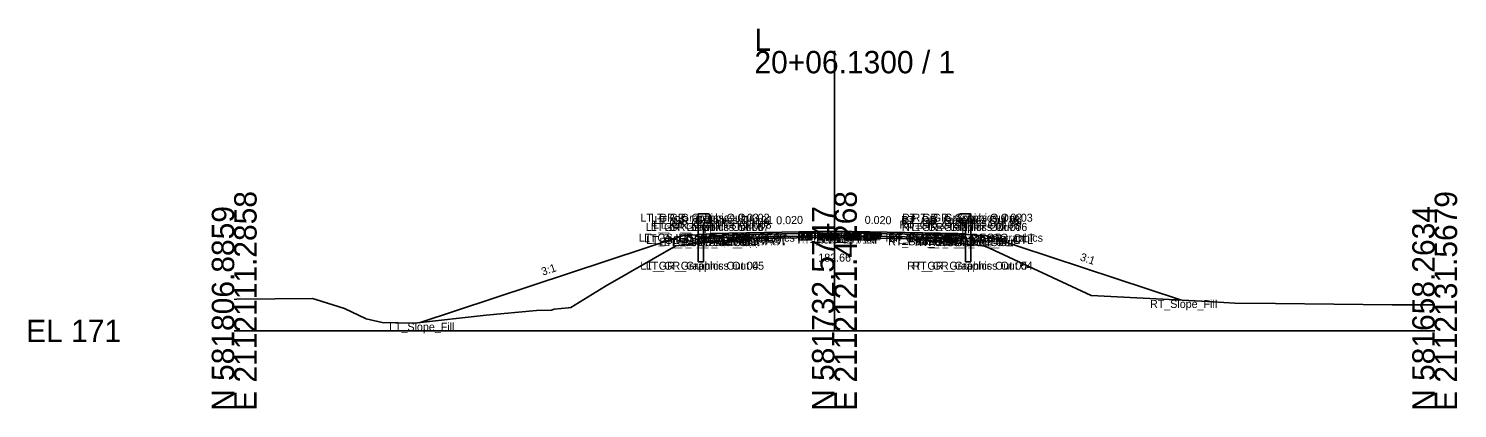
# Model space of a CAD drawing. Extents: x -26 to 3453, y -333 to 9539.
# Drawn here: x 3274.3 to 3452.8, y 1490.3 to 1537.8 of the extents above; entities that cross this region are included whole.
import ezdxf

# ---------------------------------------------------------------- set-up
doc = ezdxf.new("R2010")
doc.units = 0
for name, color, linetype in [('Default', 7, 'Continuous'), ('Exist Cross Section Cell', 7, 'Continuous'), ('Exist XS Ground Line', 7, 'Continuous'), ('Prop CMT Guardrail Graphics', 7, 'Continuous'), ('Prop CMT Pvmt Course 1', 7, 'Continuous'), ('Prop CMT Pvmt Course 2', 7, 'Continuous'), ('Prop CMT Pvmt Course 3', 7, 'Continuous'), ('Prop CMT Pvmt Surface', 7, 'Continuous'), ('Prop CMT Pvmt Surface Shoulder', 7, 'Continuous'), ('Prop CMT Shld Paved Course 1', 7, 'Continuous'), ('Prop CMT Shld Paved Course 2', 7, 'Continuous'), ('Prop CMT Shld Paved Course 3', 7, 'Continuous'), ('Prop CMT Slope Grass', 7, 'Continuous'), ('Prop CMT Subgrade Earthwork', 7, 'Continuous'), ('Prop XS SE Text', 7, 'Continuous'), ('Prop XS Side Slope Text', 7, 'Continuous'), ('Scratch_Level_0', 7, 'Continuous')]:
    doc.layers.add(name, color=color, linetype=linetype)

msp = doc.modelspace()

# ---------------------------------------------------------------- linework, layer by layer
at = {"layer": 'Exist Cross Section Cell'}
for p, q in [((3375, 1500), (3375, 1535)), ((3300, 1500), (3375, 1500)), ((3375, 1500), (3450, 1500))]:
    msp.add_line(p, q, dxfattribs=at)
at = {"layer": 'Exist XS Ground Line'}
msp.add_lwpolyline([(3300, 1503.93), (3300.34, 1503.95), (3305.1, 1504.01), (3309.8, 1504.07), (3310.22, 1503.93), (3313.78, 1502.78), (3316.49, 1501.5), (3318.49, 1501.07), (3322.53, 1500.95), (3331.47, 1501.95), (3337.77, 1502.56), (3339.66, 1502.61), (3339.97, 1502.7), (3341.73, 1502.87), (3342.06, 1502.93), (3346.4, 1505.58), (3355.19, 1510.64), (3357.41, 1510.88), (3361.76, 1511.29), (3365.33, 1511.55), (3370.29, 1511.63), (3374.88, 1511.67), (3379.97, 1511.59), (3384.64, 1511.51), (3392.84, 1510.71), (3393.76, 1510.6), (3394.38, 1510.33), (3407.09, 1504.42), (3420.9, 1503.73), (3425.02, 1503.46), (3430.12, 1503.42), (3444.68, 1503.24), (3450, 1503.24)], dxfattribs=at)
at = {"layer": 'Prop CMT Guardrail Graphics'}
for points in [[(3357.97, 1508.65), (3357.97, 1514.65)], [(3357.97, 1514.65), (3359.3, 1514.65), (3359.57, 1514.36)], [(3359.57, 1514.36), (3359.3, 1514.07)], [(3359.3, 1514.07), (3359.57, 1513.78)], [(3392.03, 1514.65), (3390.7, 1514.65), (3390.43, 1514.36)], [(3390.43, 1514.36), (3390.7, 1514.07)], [(3390.7, 1514.07), (3390.43, 1513.78)], [(3392.03, 1508.65), (3392.03, 1514.65)], [(3359.57, 1513.78), (3359.3, 1513.49), (3358.64, 1513.49)], [(3358.64, 1513.49), (3358.64, 1508.65)], [(3390.43, 1513.78), (3390.7, 1513.49), (3391.36, 1513.49)], [(3391.36, 1513.49), (3391.36, 1508.65)], [(3358.64, 1508.65), (3357.97, 1508.65)], [(3391.36, 1508.65), (3392.03, 1508.65)]]:
    msp.add_lwpolyline(points, dxfattribs=at)
at = {"layer": 'Prop CMT Pvmt Course 1'}
for points in [[(3375, 1512.46), (3364, 1512.24)], [(3364, 1512.04), (3375, 1512.26)], [(3364, 1512.24), (3364, 1512.04)], [(3375, 1512.26), (3375, 1512.46)], [(3375, 1512.46), (3386, 1512.24)], [(3375, 1512.26), (3375, 1512.46)], [(3386, 1512.04), (3375, 1512.26)], [(3386, 1512.24), (3386, 1512.04)]]:
    msp.add_lwpolyline(points, dxfattribs=at)
msp.add_lwpolyline([(3375, 1512.26), (3375, 1512.34), (3375, 1512.34), (3375, 1512.26)], close=True, dxfattribs=at)
msp.add_lwpolyline([(3375, 1512.26), (3375, 1512.34), (3375, 1512.34), (3375, 1512.26)], close=True, dxfattribs=at)
at = {"layer": 'Prop CMT Pvmt Course 2'}
for points in [[(3375, 1512.26), (3364, 1512.04)], [(3375, 1511.92), (3375, 1512.26)], [(3375, 1511.92), (3375, 1512.26)], [(3375, 1512.26), (3386, 1512.04)], [(3364, 1512.04), (3364, 1511.7)], [(3364, 1511.7), (3375, 1511.92)], [(3386, 1511.7), (3375, 1511.92)], [(3386, 1512.04), (3386, 1511.7)]]:
    msp.add_lwpolyline(points, dxfattribs=at)
at = {"layer": 'Prop CMT Pvmt Course 3'}
for points in [[(3375, 1511.92), (3364, 1511.7)], [(3364, 1511.7), (3375, 1511.92)], [(3364, 1511.7), (3364, 1511.7)], [(3375, 1511.92), (3375, 1511.92)], [(3375, 1511.92), (3386, 1511.7)], [(3386, 1511.7), (3375, 1511.92)], [(3375, 1511.92), (3375, 1511.92)], [(3386, 1511.7), (3386, 1511.7)]]:
    msp.add_lwpolyline(points, dxfattribs=at)
at = {"layer": 'Prop CMT Pvmt Surface'}
for points in [[(3375, 1512.46), (3364, 1512.24)], [(3375, 1512.46), (3386, 1512.24)]]:
    msp.add_lwpolyline(points, dxfattribs=at)
at = {"layer": 'Prop CMT Pvmt Surface Shoulder'}
for points in [[(3364, 1512.24), (3359.58, 1512.16)], [(3386, 1512.24), (3390.42, 1512.16)]]:
    msp.add_lwpolyline(points, dxfattribs=at)
at = {"layer": 'Prop CMT Shld Paved Course 1'}
for points in [[(3364, 1512.24), (3359.58, 1512.16), (3359.37, 1511.94)], [(3364, 1512.04), (3364, 1512.24)], [(3386, 1512.24), (3390.42, 1512.16), (3390.63, 1511.94)], [(3386, 1512.04), (3386, 1512.24)], [(3359.37, 1511.94), (3364, 1512.04)], [(3390.63, 1511.94), (3386, 1512.04)]]:
    msp.add_lwpolyline(points, dxfattribs=at)
at = {"layer": 'Prop CMT Shld Paved Course 2'}
for points in [[(3364, 1512.04), (3359.37, 1511.94), (3359.03, 1511.6)], [(3359.03, 1511.6), (3364, 1511.7)], [(3364, 1511.7), (3364, 1512.04)], [(3386, 1512.04), (3390.63, 1511.94), (3390.97, 1511.6)], [(3386, 1511.7), (3386, 1512.04)], [(3390.97, 1511.6), (3386, 1511.7)]]:
    msp.add_lwpolyline(points, dxfattribs=at)
at = {"layer": 'Prop CMT Shld Paved Course 3'}
for points in [[(3364, 1511.7), (3359.03, 1511.6)], [(3359.03, 1511.6), (3364, 1511.7)], [(3359.03, 1511.6), (3359.03, 1511.6), (3359.03, 1511.6)], [(3364, 1511.7), (3364, 1511.7)], [(3386, 1511.7), (3390.97, 1511.6)], [(3390.97, 1511.6), (3386, 1511.7)], [(3386, 1511.7), (3386, 1511.7)], [(3390.97, 1511.6), (3390.97, 1511.6), (3390.97, 1511.6)]]:
    msp.add_lwpolyline(points, dxfattribs=at)
at = {"layer": 'Prop CMT Slope Grass'}
for points in [[(3356, 1511.87), (3323.1, 1501.01)], [(3359.57, 1512.15), (3356, 1511.87)], [(3359.58, 1512.16), (3359.57, 1512.15)], [(3390.42, 1512.16), (3390.43, 1512.15)], [(3390.43, 1512.15), (3394, 1511.87)], [(3394, 1511.87), (3418.25, 1503.87)]]:
    msp.add_lwpolyline(points, dxfattribs=at)
at = {"layer": 'Prop CMT Subgrade Earthwork'}
for points in [[(3359.03, 1511.6), (3358.56, 1512.07)], [(3364, 1511.7), (3359.03, 1511.6)], [(3375, 1511.92), (3364, 1511.7)], [(3375, 1511.92), (3386, 1511.7)], [(3386, 1511.7), (3390.97, 1511.6)], [(3390.97, 1511.6), (3391.44, 1512.07)]]:
    msp.add_lwpolyline(points, dxfattribs=at)

# ---------------------------------------------------------------- texts
at = {"layer": 'Default'}
msp.add_text('-', height=0.0001, dxfattribs=at).set_placement((3300, 1500))
at = {"layer": 'Exist Cross Section Cell'}
for s, p in [('L', (3365, 1535)), ('20+06.1300 / 1', (3365, 1532.2)), ('EL 171', (3274, 1498.6))]:
    msp.add_text(s, height=2.8, dxfattribs=at).set_placement(p)
for s, p in [('E 2112111.2858', (3302.8, 1490)), ('E 2112121.4268', (3377.8, 1490)), ('E 2112131.5679', (3452.8, 1490)), ('N 581806.8859', (3300, 1490)), ('N 581732.5747', (3375, 1490)), ('N 581658.2634', (3450, 1490))]:
    msp.add_text(s, height=2.8, rotation=90, dxfattribs=at).set_placement(p)
at = {"layer": 'Exist XS Ground Line'}
msp.add_text('182.66', height=1, dxfattribs=at).set_placement((3372.98, 1508.66))
at = {"layer": 'Prop XS SE Text'}
for rotation, p in [(1.1458, (3367.73, 1513.32)), (358.8542, (3378.77, 1513.39))]:
    msp.add_text('0.020', height=1, rotation=rotation, dxfattribs=at).set_placement(p)
at = {"layer": 'Prop XS Side Slope Text'}
for rotation, p in [(341.7371, (3405.61, 1508.83)), (18.2629, (3338.56, 1506.9))]:
    msp.add_text('3:1', height=1, rotation=rotation, dxfattribs=at).set_placement(p)
at = {"layer": 'Scratch_Level_0'}
for s, p in [('LT_GR_Graphics Out 03', (3350.75, 1513.65)), ('LT_GR_Graphics Out 09', (3352.08, 1513.07)), ('LT_GR_Graphics Out 02', (3352.1, 1513.65)), ('LT_GR_Graphics Out 01', (3352.52, 1513.36)), ('RT_GR_Graphics Out 01', (3383.31, 1513.36)), ('RT_GR_Graphics Out 09', (3383.41, 1513.07)), ('RT_GR_Graphics Out 02', (3383.44, 1513.65)), ('RT_GR_Graphics Out 03', (3384.76, 1513.65)), ('LT_GS_OS_GR_Face_Graphics', (3350.57, 1511.15)), ('LT_GR_Graphics Out 06', (3351.41, 1512.49)), ('LT_GR_Graphics Out 07', (3352.06, 1512.49)), ('LT_GR_Graphics Out 08', (3352.34, 1512.78)), ('LT_PV1_OEOT', (3359.87, 1511.24)), ('RT_PV2_OEEOP', (3370.33, 1511.26)), ('LT_PV2_OEEOP', (3370.39, 1511.26)), ('RT_PV1_OEEOP', (3370.45, 1511.34)), ('LT_PV1_OEEOP', (3370.51, 1511.34)), ('RT_PV2_IEEOP', (3370.71, 1511.26)), ('LT_PV2_IEEOP', (3370.77, 1511.26)), ('RT_PV1_IEEOP', (3370.83, 1511.34)), ('LT_PV1_IEEOP', (3370.89, 1511.34)), ('PV2_PGL', (3372.35, 1511.26)), ('PV1_PGL', (3372.47, 1511.46)), ('RT_GS_OS_GR_Face_Graphics', (3381.36, 1511.15)), ('RT_PV1_OEOT', (3381.81, 1511.24)), ('RT_GR_Graphics Out 08', (3383.14, 1512.78)), ('RT_GR_Graphics Out 07', (3383.4, 1512.49)), ('RT_GR_Graphics Out 06', (3384.08, 1512.49)), ('LT_Sub_Trench_Out_DLT', (3351.21, 1511.07)), ('LT_GS_OS_CTL', (3351.46, 1510.87)), ('LT_Sub_Trench_Out', (3353.14, 1510.6)), ('LT_PS3_Shelf_Out', (3353.69, 1510.6)), ('LT_PS3_OEOP', (3354.82, 1510.6)), ('LT_PS2_OEOP', (3355.16, 1510.94)), ('LT_PS1_OEOP', (3355.49, 1511.16)), ('LT_PV2_OEOT', (3359.75, 1511.04)), ('LT_PV3_OEOT', (3359.75, 1510.7)), ('LT_Sub_OEOT', (3359.77, 1510.7)), ('RT_PV3_OEEOP', (3370.33, 1510.92)), ('RT_Sub_OEEOP', (3370.36, 1510.92)), ('LT_PV3_OEEOP', (3370.39, 1510.92)), ('LT_Sub_OEEOP', (3370.42, 1510.92)), ('RT_PV2_OEOT', (3381.69, 1511.04)), ('RT_PV3_OEOT', (3381.69, 1510.7)), ('RT_Sub_OEOT', (3381.71, 1510.7)), ('RT_Sub_Trench_Out_DLT', (3384.03, 1511.07)), ('RT_Sub_Trench_Out', (3385.02, 1510.6)), ('RT_PS3_Shelf_Out', (3385.57, 1510.6)), ('RT_PS1_OEOP', (3386.26, 1511.16)), ('RT_PS2_OEOP', (3386.36, 1510.94)), ('RT_PS3_OEOP', (3386.7, 1510.6)), ('RT_GS_OS_CTL', (3389.4, 1510.87)), ('LT_GR_Graphics Out 04', (3350.74, 1507.65)), ('LT_GR_Graphics Out 05', (3351.41, 1507.65)), ('RT_GR_Graphics Out 05', (3384.08, 1507.65)), ('RT_GR_Graphics Out 04', (3384.74, 1507.65)), ('RT_Slope_Fill', (3414.43, 1502.87)), ('LT_Slope_Fill', (3319.34, 1500.01))]:
    msp.add_text(s, height=1, dxfattribs=at).set_placement(p)

doc.saveas('drawing.dxf')
